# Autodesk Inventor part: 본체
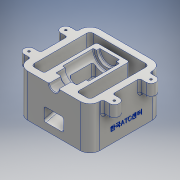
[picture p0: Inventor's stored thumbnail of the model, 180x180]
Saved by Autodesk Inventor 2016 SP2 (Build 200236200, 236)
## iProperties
Created: 2018-01
Part Number: 본체
Material: 알루미늄 6061
Document SubType Name: Modeling
Designer: Administrator
Density: 2.7 g/cm^3
Appearance: 알루미늄 - 평지
Mass: 988.682 g
Surface Area: 837.246 cm^2
Volume: 366.178 cm^3
Author: Administrator
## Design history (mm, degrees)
sketch "스케치1"
  geometry: L1 (-40, 55)-(40, 55); L2 (55, 40)-(55, -40); L3 (40, -55)-(-40, -55); L4 (-55, -40)-(-55, 40); L5 (-55, 55)-(55, -55); L6 (55, 55)-(-55, -55); L7 (40, 45)-(-40, 45); L8 (-45, 40)-(-45, -40); L9 (-40, -45)-(40, -45); L10 (45, -40)-(45, 40); A1 r 15 centre (-40, 40) between (-40, 55) and (-55, 40); A2 r 15 centre (40, 40) between (55, 40) and (40, 55); A3 r 15 centre (40, -40) between (40, -55) and (55, -40); A4 r 15 centre (-40, -40) between (-55, -40) and (-40, -55); A5 r 5 centre (-40, 40) between (-40, 45) and (-45, 40); A6 r 5 centre (40, 40) between (45, 40) and (40, 45); A7 r 5 centre (40, -40) between (40, -45) and (45, -40); A8 r 5 centre (-40, -40) between (-45, -40) and (-40, -45); 1 further point
  constraints: 20 end point, 16 point on circle, 16 tangent, 8 centre point, 8 point on line, 6 equal radius, 4 parallel, 2 midpoint, 2 perpendicular, 1 horizontal, 3 other
  dimensions: "d0" = 110 distance of L5.end L6.end; "d1" = 110 distance of L6.start L5.end; "d2" = 10 distance between parallel lines of L1 L7; "d3" = 15 radius of A1; "d4" = 5 radius of A5
extrude "돌출1" new body sketch "스케치1" distance "d5" = 65; taper "d6" = 0 deg
sketch "스케치2"
  geometry: L1 (-40, -55)-(40, -55) reference; L2 (-55, 40)-(-55, -40) reference; L3 (55, -40)-(55, 40) reference; L4 (-65, 35.5)-(-48.474, 35.5); L5 (-65, 20.5)-(-48.474, 20.5); L6 (-65, -20.5)-(-48.474, -20.5); L7 (-48.474, -20.5)-(-48.474, -35.5); L8 (-48.474, -35.5)-(-65, -35.5); L9 (65, -20.5)-(47.99, -20.5); L10 (47.99, -20.5)-(47.99, -35.5); L11 (47.99, -35.5)-(65, -35.5); L12 (65, 20.5)-(47.99, 20.5); L13 (47.99, 20.5)-(47.99, 35.5); L14 (47.99, 35.5)-(65, 35.5); L15 (-48.474, 20.5)-(-48.474, 35.5); A1 r 7.5 centre (-65, 28) between (-65, 35.5) and (-65, 20.5); A2 r 7.5 centre (-65, -28) between (-65, -20.5) and (-65, -35.5); A3 r 7.5 centre (65, 28) between (65, 20.5) and (65, 35.5); A4 r 7.5 centre (65, -28) between (65, -35.5) and (65, -20.5); 2 further points
  constraints: 24 end point, 8 point on circle, 7 point on line, 5 horizontal, 5 tangent, 4 centre point, 2 horizontal alignment, 2 perpendicular, 2 vertical, 2 vertical alignment, 1 midpoint
  dimensions: "d7" = 15 diameter of A1; "d8" = 15 diameter of A2; "d9" = 15 diameter of A3; "d10" = 15 diameter of A4; "d11" = 27 distance from line of A2.centre L1; "d12" = 56 distance of A1.centre A2.centre; "d13" = 10 distance from line of A1.centre L2; "d14" = 10 distance from line of A3.centre L3
extrude "돌출2" join sketch "스케치2" distance "d15" = 20; taper "d16" = 0 deg
sketch "스케치3"
  geometry: L1 (-55, -35.5)-(-55, -40) reference; L2 (-40, -55)-(40, -55) reference; L3 (55, -40)-(55, -35.5) reference; L4 (65, -35.5)-(55, -35.5) reference; L5 (55, -20.5)-(65, -20.5) reference; L6 (55, -20.5)-(55, 20.5) reference; L7 (55, 20.5)-(65, 20.5) reference; L8 (65, 35.5)-(55, 35.5) reference; L9 (55, 35.5)-(55, 40) reference; L10 (40, 55)-(-40, 55) reference; L11 (-55, 40)-(-55, 35.5) reference; L12 (-55, 35.5)-(-65, 35.5) reference; L13 (-65, 20.5)-(-55, 20.5) reference; L14 (-55, 20.5)-(-55, -20.5) reference; L15 (-55, -20.5)-(-65, -20.5) reference; L16 (-65, -35.5)-(-55, -35.5) reference; L17 (-40, 45)-(40, 45) reference; L18 (45, 40)-(45, -40) reference; L19 (40, -45)-(-40, -45) reference; L20 (-45, -40)-(-45, 40) reference; A1 r 15 centre (-40, -40) between (-55, -40) and (-40, -55) reference; A2 r 15 centre (40, -40) between (40, -55) and (55, -40) reference; A3 r 7.5 centre (65, -28) between (65, -35.5) and (65, -20.5) reference; A4 r 7.5 centre (65, 28) between (65, 20.5) and (65, 35.5) reference; A5 r 15 centre (40, 40) between (55, 40) and (40, 55) reference; A6 r 15 centre (-40, 40) between (-40, 55) and (-55, 40) reference; A7 r 7.5 centre (-65, 28) between (-65, 35.5) and (-65, 20.5) reference; A8 r 7.5 centre (-65, -28) between (-65, -20.5) and (-65, -35.5) reference; A9 r 5 centre (-40, 40) between (-40, 45) and (-45, 40) reference; A10 r 5 centre (40, 40) between (45, 40) and (40, 45) reference; A11 r 5 centre (40, -40) between (40, -45) and (45, -40) reference; A12 r 5 centre (-40, -40) between (-45, -40) and (-40, -45) reference; 5 further points
  constraints: 4 coincident
hole "구멍1" sketch "스케치3" at (-65, 28), (-65, -28), (65, -28), (65, 28) diameter "d17" = 3.242; stored, may be unused: countersink angle "d21" = 90 deg, drill point angle "d23" = 118 deg; dims "d18" = 9, "d19" = 4, "d20" = 2, "d22" = 11
sketch "스케치6"
  geometry: L1 (-51.166, 6.912)-(35, 30); L2 (35, 30)-(35, 65); L3 (-40, 65)-(40, 65) reference; L4 (-40, 65)-(-55, 65) reference; L5 (-51.166, 65)-(-51.166, 6.912); L6 (40, 0)-(-40, 0) reference; L7 (55, 0)-(55, 65) reference; 1 further point
  constraints: 6 end point, 2 point on line, 1 perpendicular, 1 vertical
  dimensions: "d27" = 105 deg angle of L5 L1; "d28" = 30 distance from line of L1.end L6; "d29" = 20 distance between parallel lines of L2 L7; "d30" = 86.16553 distance between parallel lines of L5 L2
extrude "돌출3" join sketch "스케치6" stored distance "d31" = 50; taper "d32" = 0 deg
sketch "스케치8"
  geometry: L1 (-55, 0)-(-55, 65) reference; L2 (-55, 57.5)-(-36, 57.5); L3 (-40, 0)-(-40, 65) reference; L4 (-22, 45)-(25, 45); L5 (-45, 65)-(35, 65) reference; L6 (-40, 65)-(-55, 65) reference; L7 (30, 65)-(-55, 65); L8 (-36, 57.5)-(-36, 49); L9 (-36, 49)-(-22, 49); L10 (-22, 49)-(-22, 45); L11 (25, 45)-(25, 50); L12 (25, 50)-(30, 50); L13 (20.5, 65)-(20.5, 45) reference; L14 (30, 50)-(30, 65); 2 further points
  constraints: 18 end point, 4 vertical, 2 horizontal, 2 perpendicular, 2 point on line, 1 collinear
  dimensions: "d34" = 15 diameter of L2 L7; "d35" = 32 diameter of L9 L7; "d37" = 40 diameter of L4 L7; "d38" = 30 diameter of L12 L7; "d39" = 19 distance between parallel lines of L1 L8; "d40" = 14 distance between parallel lines of L8 L10; "d41" = 47 distance between parallel lines of L10 L11; "d42" = 5 distance between parallel lines of L14 L11
revolve "회전1" sketch "스케치8" stored, may be unused: angle "d43" = 90 deg
sketch "스케치9"
  geometry: L1 (20, 31.157)-(20, 58.635); L2 (20, 58.635)-(-17, 58.635); L3 (-17, 58.635)-(-17, 41.48); L4 (-17, 41.48)-(-61.053, 29.676); L5 (20, 31.157)-(-61.053, 9.439); L6 (-61.053, 9.439)-(-61.053, 29.676); L7 (-55, 0)-(-55, 65) reference; L8 (35, 30)-(-45, 8.564) reference; L9 (-22, 45)-(25, 45) reference; 2 further points
  constraints: 12 end point, 2 parallel, 2 perpendicular, 1 midpoint, 1 vertical
  dimensions: "d44" = 5 distance from line of L8 L5.end; "d46" = 37 distance between parallel lines of L3 L1; "d48" = 13.63477 distance between parallel lines of L9 L2; "d49" = 75 distance between parallel lines of L1 L7; "d64" = 75 deg angle of L7 L4; "d65" = 6.05333 distance between parallel lines of L6 L7; "d66" = 19.54743 distance between parallel lines of L5 L4
extrude "돌출4" cut sketch "스케치9" stored distance "d51" = 30; taper "d52" = 0 deg
sketch "스케치10"
  geometry: 1 further point
node "작업 평면2"
sketch "스케치11"
  geometry: L1 (-40, 0)-(40, 0) reference; 2 further points
  constraints: 1 vertical alignment, 1 other
  dimensions: "d55" = 20 distance from line of point (0, 20) L1
feature "엠보싱1" sketch "스케치11" dims "d0" = 110, "d1" = 110, "d2" = 10, "d3" = 15, "d4" = 5, "d56" = 0.5, "d57" = 0
fillet "모깎기1" dims "d58" = 3, "d59" = 1
fillet "모깎기2" dims "d60" = 3
chamfer "모따기1" distance "d61" = 1; stored, may be unused: second distance "d62" = 2, angle "d63" = 45 deg
sketch "스케치12"
  geometry: 1 further point
fillet "모깎기3" dims "d67" = 3
node "솔리드1"
node "투영된 루프1"
